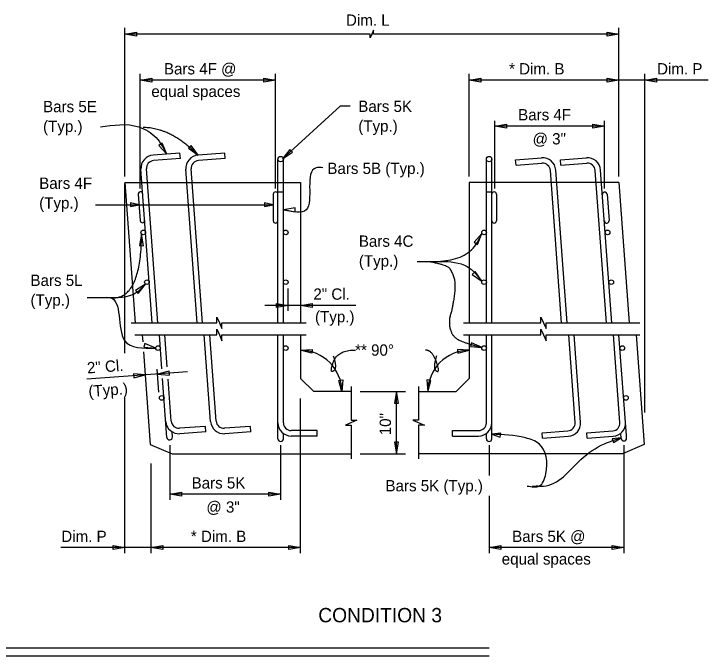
# Model space of a CAD drawing. Extents: x 120790.7 to 120844.8, y 120612.1 to 120653.6.
# Drawn here: x 120810.92 to 120820.21, y 120612.48 to 120621.08 of the extents above; entities that cross this region are included whole.
import ezdxf

# ---------------------------------------------------------------- set-up
doc = ezdxf.new("R2010")
doc.units = 0
for name, color, linetype in [('AdhocPoint_dp', 7, 'Continuous'), ('Patterning', 7, 'Continuous'), ('PlotBorder_dp', 7, 'Continuous'), ('SheetBorder_dp', 7, 'Continuous')]:
    doc.layers.add(name, color=color, linetype=linetype)

# ---------------------------------------------------------------- blocks, each defined once
blk = doc.blocks.new('Terminator-Arrow')
at = {"layer": 'PlotBorder_dp'}
blk.add_lwpolyline([(0, 0), (-0.00041, 0.000069), (-0.00041, -0.000069)], close=True, dxfattribs=at)

msp = doc.modelspace()

# ---------------------------------------------------------------- linework, layer by layer
at = {"layer": 'AdhocPoint_dp'}
for p, q in [((120812.4041, 120618.8231), (120814.7549, 120618.8231)), ((120812.4041, 120618.8231), (120812.5428, 120616.9451)), ((120814.7549, 120618.8231), (120814.7549, 120616.9451)), ((120819.012, 120618.8231), (120817.012, 120618.8231)), ((120817.012, 120618.8231), (120817.012, 120616.9451)), ((120819.012, 120618.8231), (120819.1507, 120616.9451)), ((120812.6373, 120616.7834), (120812.644, 120616.6926)), ((120814.7549, 120616.7834), (120814.7549, 120616.2012)), ((120817.012, 120616.7834), (120817.012, 120616.2012)), ((120819.2452, 120616.7834), (120819.3535, 120615.3161)), ((120812.6539, 120616.559), (120812.7457, 120615.3161)), ((120814.9317, 120616.0244), (120814.7549, 120616.2012)), ((120816.8352, 120616.0244), (120817.012, 120616.2012)), ((120815.4322, 120616.0244), (120814.9317, 120616.0244)), ((120816.3346, 120616.0244), (120816.8352, 120616.0244)), ((120812.7457, 120615.3161), (120813.0374, 120615.1911)), ((120819.3535, 120615.3161), (120819.0619, 120615.1911)), ((120813.0374, 120615.1911), (120815.4322, 120615.1911)), ((120819.0619, 120615.1911), (120816.3346, 120615.1911))]:
    msp.add_line(p, q, dxfattribs=at)
at = {"layer": 'PlotBorder_dp'}
for p, q in [((120812.4041, 120618.9059), (120812.4041, 120620.8956)), ((120812.4041, 120618.9059), (120812.4041, 120620.8956)), ((120819.012, 120618.9059), (120819.012, 120620.8956)), ((120819.012, 120618.9059), (120819.012, 120620.8956)), ((120812.6116, 120618.7443), (120812.6116, 120620.2796)), ((120812.6116, 120618.7443), (120812.6116, 120620.2796)), ((120814.4215, 120618.7443), (120814.4215, 120620.2796)), ((120814.4215, 120618.7443), (120814.4215, 120620.2796)), ((120817.012, 120618.9059), (120817.012, 120620.2796)), ((120817.012, 120618.9059), (120817.012, 120620.2796)), ((120819.3628, 120615.7466), (120819.3628, 120620.2796)), ((120819.3628, 120615.7466), (120819.3628, 120620.2796)), ((120814.4214, 120620.1951), (120812.6115, 120620.1951)), ((120814.4214, 120620.1951), (120812.6115, 120620.1951)), ((120820.2078, 120620.1951), (120817.0118, 120620.1951)), ((120820.2078, 120620.1951), (120817.0118, 120620.1951)), ((120817.3542, 120618.7443), (120817.3542, 120619.6506)), ((120817.3542, 120618.7443), (120817.3542, 120619.6506)), ((120818.823, 120619.58), (120817.3542, 120619.58)), ((120818.823, 120619.58), (120817.3542, 120619.58)), ((120818.823, 120618.7443), (120818.823, 120619.6506)), ((120818.823, 120618.7443), (120818.823, 120619.6506)), ((120812.4041, 120616.5376), (120812.4041, 120618.8093)), ((120812.4041, 120616.5376), (120812.4041, 120618.8093)), ((120812.0106, 120618.527), (120814.3903, 120618.527)), ((120812.0106, 120618.527), (120814.3903, 120618.527)), ((120814.5882, 120617.1047), (120814.5882, 120617.405)), ((120814.5882, 120617.1047), (120814.5882, 120617.405)), ((120815.4972, 120617.1797), (120814.2782, 120617.1797)), ((120815.4972, 120617.1797), (120814.2782, 120617.1797)), ((120812.8612, 120616.0158), (120812.8384, 120616.325)), ((120812.8612, 120616.0158), (120812.8384, 120616.325)), ((120813.2437, 120616.2903), (120811.8962, 120616.1908)), ((120813.2437, 120616.2903), (120811.8962, 120616.1908)), ((120815.5533, 120616.0244), (120816.1614, 120616.0244)), ((120815.5533, 120616.0244), (120816.1614, 120616.0244)), ((120816.0406, 120615.1911), (120816.0406, 120616.0244)), ((120816.0406, 120615.1911), (120816.0406, 120616.0244)), ((120812.4041, 120613.8613), (120812.4041, 120615.9404)), ((120812.4041, 120613.8613), (120812.4041, 120615.9404)), ((120814.7549, 120613.8613), (120814.7549, 120615.9327)), ((120814.7549, 120613.8613), (120814.7549, 120615.9327)), ((120813.0046, 120615.3084), (120813.0046, 120614.5766)), ((120813.0046, 120615.3084), (120813.0046, 120614.5766)), ((120814.4893, 120615.3084), (120814.4893, 120614.5766)), ((120814.4893, 120615.3084), (120814.4893, 120614.5766)), ((120817.2776, 120615.3084), (120817.2776, 120614.9019)), ((120817.2776, 120615.3084), (120817.2776, 120614.9019)), ((120819.0809, 120615.3084), (120819.0809, 120613.8613)), ((120819.0809, 120615.3084), (120819.0809, 120613.8613)), ((120815.5533, 120615.1911), (120816.1614, 120615.1911)), ((120815.5533, 120615.1911), (120816.1614, 120615.1911)), ((120812.7549, 120613.8613), (120812.7549, 120615.0633)), ((120812.7549, 120613.8613), (120812.7549, 120615.0633)), ((120814.4893, 120614.6522), (120813.0046, 120614.6522)), ((120814.4893, 120614.6522), (120813.0046, 120614.6522)), ((120817.2776, 120614.6298), (120817.2776, 120613.8613)), ((120817.2776, 120614.6298), (120817.2776, 120613.8613)), ((120814.7549, 120613.9369), (120811.5492, 120613.9369)), ((120814.7549, 120613.9369), (120811.5492, 120613.9369)), ((120819.0809, 120613.9369), (120817.2776, 120613.9369)), ((120819.0809, 120613.9369), (120817.2776, 120613.9369)), ((120817.2776, 120612.5928), (120809.1791, 120612.5928)), ((120817.2776, 120612.5928), (120809.1791, 120612.5928)), ((120817.2776, 120612.4847), (120809.1791, 120612.4847)), ((120817.2776, 120612.4847), (120809.1791, 120612.4847))]:
    msp.add_line(p, q, dxfattribs=at)
for points in [[(120819.0118, 120620.8104), (120815.7303, 120620.8104), (120815.7303, 120620.8621), (120815.7078, 120620.8104), (120815.6853, 120620.7588), (120815.6853, 120620.8104), (120812.404, 120620.8104)], [(120819.0118, 120620.8104), (120815.7303, 120620.8104), (120815.7303, 120620.8621), (120815.7078, 120620.8104), (120815.6853, 120620.7588), (120815.6853, 120620.8104), (120812.404, 120620.8104)], [(120815.419, 120619.8458), (120815.286, 120619.8458), (120814.5144, 120619.1427)], [(120815.419, 120619.8458), (120815.286, 120619.8458), (120814.5144, 120619.1427)], [(120812.4899, 120616.9451), (120813.6369, 120616.9451), (120813.6369, 120617.0226), (120813.6707, 120616.9451), (120813.7044, 120616.8676), (120813.7044, 120616.9451), (120814.8305, 120616.9451)], [(120812.4899, 120616.9451), (120813.6369, 120616.9451), (120813.6369, 120617.0226), (120813.6707, 120616.9451), (120813.7044, 120616.8676), (120813.7044, 120616.9451), (120814.8305, 120616.9451)], [(120816.9364, 120616.9451), (120817.9717, 120616.9451), (120817.9717, 120617.0226), (120818.0054, 120616.9451), (120818.0392, 120616.8676), (120818.0392, 120616.9451), (120819.2965, 120616.9451)], [(120816.9364, 120616.9451), (120817.9717, 120616.9451), (120817.9717, 120617.0226), (120818.0054, 120616.9451), (120818.0392, 120616.8676), (120818.0392, 120616.9451), (120819.2965, 120616.9451)], [(120812.5373, 120616.7834), (120813.6369, 120616.7834), (120813.6369, 120616.8609), (120813.6707, 120616.7834), (120813.7044, 120616.7059), (120813.7044, 120616.7834), (120814.8305, 120616.7834)], [(120812.5373, 120616.7834), (120813.6369, 120616.7834), (120813.6369, 120616.8609), (120813.6707, 120616.7834), (120813.7044, 120616.7059), (120813.7044, 120616.7834), (120814.8305, 120616.7834)], [(120816.9364, 120616.7834), (120817.9717, 120616.7834), (120817.9717, 120616.8609), (120818.0054, 120616.7834), (120818.0392, 120616.7059), (120818.0392, 120616.7834), (120819.2965, 120616.7834)], [(120816.9364, 120616.7834), (120817.9717, 120616.7834), (120817.9717, 120616.8609), (120818.0054, 120616.7834), (120818.0392, 120616.7059), (120818.0392, 120616.7834), (120819.2965, 120616.7834)], [(120815.4322, 120616.0915), (120815.4322, 120615.6415), (120815.5097, 120615.6415), (120815.3547, 120615.574), (120815.4322, 120615.574), (120815.4322, 120615.124)], [(120815.4322, 120616.0915), (120815.4322, 120615.6415), (120815.5097, 120615.6415), (120815.3547, 120615.574), (120815.4322, 120615.574), (120815.4322, 120615.124)], [(120816.3346, 120616.0915), (120816.3346, 120615.6415), (120816.2571, 120615.6415), (120816.4121, 120615.574), (120816.3346, 120615.574), (120816.3346, 120615.124)], [(120816.3346, 120616.0915), (120816.3346, 120615.6415), (120816.2571, 120615.6415), (120816.4121, 120615.574), (120816.3346, 120615.574), (120816.3346, 120615.124)]]:
    msp.add_lwpolyline(points, dxfattribs=at)
for points in [[(120812.9647, 120619.2035), (120812.9026, 120619.3492), (120812.8581, 120619.3207)], [(120812.9647, 120619.2035), (120812.9026, 120619.3492), (120812.8581, 120619.3207)], [(120813.3849, 120619.19), (120813.2935, 120619.3194), (120813.256, 120619.282)], [(120813.3849, 120619.19), (120813.2935, 120619.3194), (120813.256, 120619.282)], [(120814.5144, 120619.1428), (120814.6477, 120619.2284), (120814.6121, 120619.2675)], [(120814.5144, 120619.1428), (120814.6477, 120619.2284), (120814.6121, 120619.2675)], [(120812.5958, 120618.527), (120812.4786, 120618.5535), (120812.4786, 120618.5005)], [(120812.5958, 120618.527), (120812.4786, 120618.5535), (120812.4786, 120618.5005)], [(120814.3903, 120618.527), (120814.2732, 120618.5535), (120814.2732, 120618.5005)], [(120814.3903, 120618.527), (120814.2732, 120618.5535), (120814.2732, 120618.5005)], [(120814.5257, 120618.4585), (120814.6819, 120618.432), (120814.6819, 120618.485)], [(120814.5257, 120618.4585), (120814.6819, 120618.432), (120814.6819, 120618.485)], [(120812.6297, 120618.1344), (120812.6016, 120617.9785), (120812.6546, 120617.9779)], [(120812.6297, 120618.1344), (120812.6016, 120617.9785), (120812.6546, 120617.9779)], [(120817.1821, 120618.1422), (120817.0763, 120618.0242), (120817.1211, 120617.996)], [(120817.1821, 120618.1422), (120817.0763, 120618.0242), (120817.1211, 120617.996)], [(120817.1817, 120617.5033), (120817.0896, 120617.6322), (120817.0523, 120617.5947)], [(120817.1817, 120617.5033), (120817.0896, 120617.6322), (120817.0523, 120617.5947)], [(120812.682, 120617.4651), (120812.5494, 120617.3784), (120812.5853, 120617.3396)], [(120812.682, 120617.4651), (120812.5494, 120617.3784), (120812.5853, 120617.3396)], [(120812.8175, 120616.6078), (120812.6721, 120616.6707), (120812.6595, 120616.6193)], [(120812.8175, 120616.6078), (120812.6721, 120616.6707), (120812.6595, 120616.6193)], [(120817.1869, 120616.6139), (120817.0423, 120616.6784), (120817.0291, 120616.6272)], [(120817.1869, 120616.6139), (120817.0423, 120616.6784), (120817.0291, 120616.6272)], [(120814.7548, 120616.5779), (120814.9127, 120616.5909), (120814.9082, 120616.5382)], [(120814.7548, 120616.5779), (120814.9127, 120616.5909), (120814.9082, 120616.5382)], [(120817.012, 120616.5779), (120816.8541, 120616.5909), (120816.8586, 120616.5382)], [(120817.012, 120616.5779), (120816.8541, 120616.5909), (120816.8586, 120616.5382)], [(120812.6768, 120616.2485), (120812.5191, 120616.2633), (120812.523, 120616.2106)], [(120812.6768, 120616.2485), (120812.5191, 120616.2633), (120812.523, 120616.2106)], [(120812.8431, 120616.2607), (120813.0008, 120616.2459), (120812.9969, 120616.2986)], [(120812.8431, 120616.2607), (120813.0008, 120616.2459), (120812.9969, 120616.2986)], [(120815.3096, 120616.0226), (120815.2685, 120616.1755), (120815.3212, 120616.1806)], [(120815.3096, 120616.0226), (120815.2685, 120616.1755), (120815.3212, 120616.1806)], [(120816.4572, 120616.0226), (120816.4984, 120616.1755), (120816.4457, 120616.1806)], [(120816.4572, 120616.0226), (120816.4984, 120616.1755), (120816.4457, 120616.1806)], [(120816.0406, 120616.0244), (120816.0142, 120615.8683), (120816.0671, 120615.8683)], [(120816.0406, 120616.0244), (120816.0142, 120615.8683), (120816.0671, 120615.8683)], [(120817.3141, 120615.455), (120817.4276, 120615.4159), (120817.4334, 120615.4686)], [(120817.3141, 120615.455), (120817.4276, 120615.4159), (120817.4334, 120615.4686)], [(120819.044, 120615.4064), (120818.9248, 120615.3918), (120818.9426, 120615.342)], [(120819.044, 120615.4064), (120818.9248, 120615.3918), (120818.9426, 120615.342)], [(120816.0406, 120615.1912), (120816.0671, 120615.3474), (120816.0142, 120615.3474)], [(120816.0406, 120615.1912), (120816.0671, 120615.3474), (120816.0142, 120615.3474)]]:
    msp.add_lwpolyline(points, close=True, dxfattribs=at)
for centre, start, end in [((120814.7505, 120616.0187), 0.39914, 89.54996), ((120814.7505, 120616.0187), 0.39914, 89.54996), ((120817.0164, 120616.0187), 90.45004, 179.60086), ((120817.0164, 120616.0187), 90.45004, 179.60086)]:
    msp.add_arc(centre, 0.5592, start, end, dxfattribs=at)
for points in [[(120812.0777, 120619.5681), (120812.5921, 120619.5681), (120812.8222, 120619.4255), (120812.9647, 120619.2034)], [(120812.0777, 120619.5681), (120812.5921, 120619.5681), (120812.8222, 120619.4255), (120812.9647, 120619.2034)], [(120815.0537, 120619.0206), (120814.9639, 120619.0206), (120814.8318, 120618.4585), (120814.5257, 120618.4585)], [(120815.0537, 120619.0206), (120814.9639, 120619.0206), (120814.8318, 120618.4585), (120814.5257, 120618.4585)], [(120816.3169, 120617.7672), (120816.5689, 120617.7672), (120817.0443, 120617.9239), (120817.1821, 120618.1422)], [(120816.3169, 120617.7672), (120816.5689, 120617.7672), (120817.0443, 120617.9239), (120817.1821, 120618.1422)], [(120816.4395, 120617.7672), (120816.6303, 120617.7684), (120816.9865, 120617.6975), (120817.1817, 120617.5033)], [(120816.4395, 120617.7672), (120816.6303, 120617.7684), (120816.9865, 120617.6975), (120817.1817, 120617.5033)], [(120811.9008, 120617.2836), (120812.15, 120617.2836), (120812.5629, 120617.3549), (120812.682, 120617.4651)], [(120811.9008, 120617.2836), (120812.15, 120617.2836), (120812.5629, 120617.3549), (120812.682, 120617.4651)], [(120812.1078, 120617.2836), (120812.202, 120617.2841), (120812.4011, 120616.71), (120812.8175, 120616.6078)], [(120812.1078, 120617.2836), (120812.202, 120617.2841), (120812.4011, 120616.71), (120812.8175, 120616.6078)], [(120817.7874, 120614.7615), (120817.949, 120614.7615), (120818.0366, 120614.926), (120817.9462, 120615.3261), (120817.7655, 120615.4056), (120817.3141, 120615.4549)], [(120817.7874, 120614.7615), (120817.949, 120614.7615), (120818.0366, 120614.926), (120817.9462, 120615.3261), (120817.7655, 120615.4056), (120817.3141, 120615.4549)], [(120817.8559, 120614.7615), (120817.9627, 120614.7615), (120818.0038, 120614.7615), (120818.505, 120615.1151), (120818.8199, 120615.3261), (120819.044, 120615.4064)], [(120817.8559, 120614.7615), (120817.9627, 120614.7615), (120818.0038, 120614.7615), (120818.505, 120615.1151), (120818.8199, 120615.3261), (120819.044, 120615.4064)]]:
    msp.add_spline(points, degree=3, dxfattribs=at)
for points in [[(120813.3844, 120619.1901), (120813.0161, 120619.56), (120812.6479, 120619.56)], [(120813.3844, 120619.1901), (120813.0161, 120619.56), (120812.6479, 120619.56)], [(120812.2537, 120617.281), (120812.6208, 120617.281), (120812.6297, 120618.1344)], [(120812.2537, 120617.281), (120812.6208, 120617.281), (120812.6297, 120618.1344)], [(120816.4786, 120617.7674), (120816.6985, 120617.7219), (120816.7732, 120617.6566), (120816.8354, 120617.4605), (120816.7856, 120617.1368), (120816.7483, 120617.0216), (120816.7483, 120616.9376), (120816.7483, 120616.8847), (120816.8012, 120616.7508), (120816.9692, 120616.6699), (120817.1869, 120616.6139)], [(120816.4786, 120617.7674), (120816.6985, 120617.7219), (120816.7732, 120617.6566), (120816.8354, 120617.4605), (120816.7856, 120617.1368), (120816.7483, 120617.0216), (120816.7483, 120616.9376), (120816.7483, 120616.8847), (120816.8012, 120616.7508), (120816.9692, 120616.6699), (120817.1869, 120616.6139)], [(120815.1927, 120616.5051), (120815.25, 120616.3332), (120815.1393, 120616.2645), (120815.2519, 120616.5815), (120815.4918, 120616.5815)], [(120815.1927, 120616.5051), (120815.25, 120616.3332), (120815.1393, 120616.2645), (120815.2519, 120616.5815), (120815.4918, 120616.5815)], [(120816.5761, 120616.5051), (120816.5188, 120616.3332), (120816.6295, 120616.2645), (120816.5169, 120616.5815), (120816.426, 120616.5815)], [(120816.5761, 120616.5051), (120816.5188, 120616.3332), (120816.6295, 120616.2645), (120816.5169, 120616.5815), (120816.426, 120616.5815)]]:
    msp.add_open_spline(points, degree=2, dxfattribs=at)
at = {"layer": 'SheetBorder_dp'}
for p, q in [((120813.1426, 120619.2166), (120812.7844, 120619.1901)), ((120813.1479, 120619.1438), (120813.1426, 120619.2166)), ((120813.7426, 120619.2166), (120813.3844, 120619.1901)), ((120813.7479, 120619.1438), (120813.7426, 120619.2166)), ((120813.1479, 120619.1438), (120812.7897, 120619.1174)), ((120813.7479, 120619.1438), (120813.3897, 120619.1174)), ((120814.4528, 120616.9451), (120814.4528, 120619.1363)), ((120814.5257, 120616.9451), (120814.5257, 120619.1363)), ((120817.2411, 120616.9451), (120817.2411, 120619.1363)), ((120817.3141, 120616.9451), (120817.3141, 120619.1363)), ((120817.6332, 120619.1292), (120817.9801, 120619.1548)), ((120817.6386, 120619.0565), (120817.6332, 120619.1292)), ((120818.2332, 120619.1292), (120818.5801, 120619.1548)), ((120818.2386, 120619.0565), (120818.2332, 120619.1292)), ((120817.6386, 120619.0565), (120817.9855, 120619.0821)), ((120818.2386, 120619.0565), (120818.5855, 120619.0821)), ((120812.7725, 120616.9451), (120812.6208, 120619.0004)), ((120812.8457, 120616.9451), (120812.6935, 120619.0058)), ((120813.3725, 120616.9451), (120813.2208, 120619.0004)), ((120813.4457, 120616.9451), (120813.2935, 120619.0058)), ((120818.2478, 120616.9451), (120818.0971, 120618.9858)), ((120818.3209, 120616.9451), (120818.1698, 120618.9912)), ((120818.8478, 120616.9451), (120818.6971, 120618.9858)), ((120818.9209, 120616.9451), (120818.7698, 120618.9912)), ((120812.5827, 120618.6669), (120812.6088, 120618.3137)), ((120814.3903, 120618.6669), (120814.3903, 120618.3127)), ((120814.4528, 120618.6981), (120814.5257, 120618.6981)), ((120817.2411, 120618.6981), (120817.3141, 120618.6981)), ((120817.3766, 120618.6669), (120817.3766, 120618.3127)), ((120818.8564, 120618.6669), (120818.8825, 120618.3137)), ((120812.9004, 120616.3311), (120812.867, 120616.7834)), ((120812.9718, 120616.3554), (120812.9402, 120616.7834)), ((120813.5525, 120615.6255), (120813.467, 120616.7834)), ((120813.6253, 120615.6309), (120813.5402, 120616.7834)), ((120814.4528, 120615.3942), (120814.4528, 120616.7834)), ((120814.5257, 120615.6078), (120814.5257, 120616.7834)), ((120817.2411, 120615.6078), (120817.2411, 120616.7834)), ((120817.3141, 120615.4307), (120817.3141, 120616.7834)), ((120818.4288, 120615.611), (120818.3423, 120616.7834)), ((120818.5016, 120615.6163), (120818.4154, 120616.7834)), ((120819.0288, 120615.611), (120818.9423, 120616.7834)), ((120819.1146, 120615.4397), (120819.0154, 120616.7834)), ((120812.9683, 120615.4126), (120812.9102, 120616.1984)), ((120813.0253, 120615.6309), (120812.9838, 120616.1922)), ((120813.041, 120615.4179), (120813.0358, 120615.4881)), ((120813.4838, 120615.5603), (120813.1369, 120615.5347)), ((120813.4892, 120615.4876), (120813.1422, 120615.462)), ((120813.4892, 120615.4876), (120813.4838, 120615.5603)), ((120814.0838, 120615.5603), (120813.7369, 120615.5347)), ((120814.0892, 120615.4876), (120813.7422, 120615.462)), ((120814.0892, 120615.4876), (120814.0838, 120615.5603)), ((120814.9778, 120615.5036), (120814.6299, 120615.5036)), ((120814.9778, 120615.4307), (120814.9778, 120615.5036)), ((120816.7891, 120615.5036), (120817.1369, 120615.5036)), ((120816.7891, 120615.4307), (120816.7891, 120615.5036)), ((120817.9857, 120615.4738), (120818.3326, 120615.4994)), ((120818.5857, 120615.4738), (120818.9326, 120615.4994)), ((120814.5257, 120615.3942), (120814.5257, 120615.4646)), ((120814.9778, 120615.4307), (120814.6299, 120615.4307)), ((120816.7891, 120615.4307), (120817.1369, 120615.4307)), ((120817.2411, 120615.3942), (120817.2411, 120615.4646)), ((120817.3141, 120615.3942), (120817.3141, 120615.4307)), ((120817.991, 120615.401), (120817.9857, 120615.4738)), ((120817.991, 120615.401), (120818.338, 120615.4267)), ((120818.591, 120615.401), (120818.5857, 120615.4738)), ((120818.591, 120615.401), (120818.938, 120615.4267)), ((120819.0446, 120615.398), (120819.0394, 120615.4681)), ((120819.1173, 120615.4033), (120819.1146, 120615.4397))]:
    msp.add_line(p, q, dxfattribs=at)
for centre, radius in [((120814.4893, 120619.1374), 0.0365), ((120817.2776, 120619.1374), 0.0365), ((120812.6518, 120618.1565), 0.0312), ((120814.557, 120618.1565), 0.0312), ((120817.2099, 120618.1565), 0.0312), ((120818.8627, 120618.1565), 0.0312), ((120812.7011, 120617.4898), 0.0312), ((120814.557, 120617.4898), 0.0312), ((120817.2099, 120617.4898), 0.0312), ((120818.9119, 120617.4898), 0.0312), ((120812.8488, 120616.6078), 0.0312), ((120814.557, 120616.6078), 0.0312), ((120817.2099, 120616.6078), 0.0312), ((120819.0596, 120616.6078), 0.0312), ((120812.898, 120615.9411), 0.0312), ((120819.1088, 120615.9411), 0.0312)]:
    msp.add_circle(centre, radius, dxfattribs=at)
for centre, radius, start, end in [((120812.7974, 120619.0135), 0.1771, 94.22341, 184.22341), ((120812.7974, 120619.0135), 0.1042, 94.22341, 184.22341), ((120813.3974, 120619.0135), 0.1771, 94.22341, 184.22341), ((120813.3974, 120619.0135), 0.1042, 94.22341, 184.22341), ((120817.9932, 120618.9782), 0.1771, 4.22317, 94.22317), ((120818.5932, 120618.9782), 0.1771, 4.22317, 94.22317), ((120817.9932, 120618.9782), 0.1042, 4.22317, 94.22317), ((120818.5932, 120618.9782), 0.1042, 4.22317, 94.22317), ((120812.6139, 120618.6692), 0.0312, 4.22341, 184.22341), ((120814.4215, 120618.6669), 0.0312, 0, 180), ((120817.3453, 120618.6669), 0.0312, 0, 180), ((120818.8253, 120618.6646), 0.0312, 4.22317, 184.22317), ((120812.64, 120618.316), 0.0312, 184.22341, 4.22341), ((120814.4215, 120618.3127), 0.0312, 180, 0), ((120817.3453, 120618.3127), 0.0312, 180, 0), ((120818.8513, 120618.3114), 0.0312, 184.22317, 4.22317), ((120813.1292, 120615.6386), 0.1771, 184.22341, 274.22341), ((120813.1292, 120615.6386), 0.1042, 184.22341, 274.22341), ((120813.7292, 120615.6386), 0.1771, 184.22341, 274.22341), ((120813.7292, 120615.6386), 0.1042, 184.22341, 274.22341), ((120814.6299, 120615.6078), 0.1771, 180, 270), ((120814.6299, 120615.6078), 0.1042, 180, 270), ((120817.1369, 120615.6078), 0.1042, 270, 0), ((120817.1369, 120615.6078), 0.1771, 270, 0), ((120818.3249, 120615.6033), 0.1042, 274.22317, 4.22317), ((120818.3249, 120615.6033), 0.1771, 274.22317, 4.22317), ((120818.9249, 120615.6033), 0.1042, 274.22317, 4.22317), ((120818.9249, 120615.6033), 0.1771, 274.22317, 4.22317), ((120813.0046, 120615.4152), 0.0365, 184.22341, 4.22341), ((120814.4893, 120615.3942), 0.0365, 180, 0), ((120817.2776, 120615.3942), 0.0365, 180, 0), ((120819.0809, 120615.4007), 0.0365, 184.22317, 4.22317)]:
    msp.add_arc(centre, radius, start, end, dxfattribs=at)

# ---------------------------------------------------------------- block references
at = {"layer": 'PlotBorder_dp', "xscale": 381, "yscale": -384.0238095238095, "rotation": 180}
for p in [(120812.4038, 120620.81), (120812.4038, 120620.81), (120812.6114, 120620.1947), (120812.6114, 120620.1947), (120817.0117, 120620.1947), (120817.0117, 120620.1947), (120819.3626, 120620.195), (120819.3626, 120620.195), (120817.3541, 120619.5797), (120817.3541, 120619.5797), (120814.755, 120617.1792), (120814.755, 120617.1792), (120813.0045, 120614.6518), (120813.0045, 120614.6518), (120812.7547, 120613.9366), (120812.7547, 120613.9366), (120817.2776, 120613.9366), (120817.2776, 120613.9366)]:
    msp.add_blockref('Terminator-Arrow', p, dxfattribs=at)
at = {"layer": 'PlotBorder_dp', "xscale": 381, "yscale": -384.0238095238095}
for p in [(120819.0117, 120620.8099), (120819.0117, 120620.8099), (120814.4213, 120620.1947), (120814.4213, 120620.1947), (120819.0117, 120620.1947), (120819.0117, 120620.1947), (120818.8229, 120619.5797), (120818.8229, 120619.5797), (120814.5884, 120617.1792), (120814.5884, 120617.1792), (120814.4892, 120614.6518), (120814.4892, 120614.6518), (120812.404, 120613.9366), (120812.404, 120613.9366), (120814.7548, 120613.9366), (120814.7548, 120613.9366), (120819.0809, 120613.9366), (120819.0809, 120613.9366)]:
    msp.add_blockref('Terminator-Arrow', p, dxfattribs=at)

# ---------------------------------------------------------------- texts
at = {"layer": 'Patterning'}
for s, height, p in [('Dim. L', 0.1512, (120815.3631, 120620.9216)), ('Bars 4F @', 0.1512, (120812.9282, 120620.2703)), ('* Dim. B', 0.1512, (120817.545, 120620.2702)), ('Dim. P', 0.1512, (120819.5252, 120620.2702)), ('equal spaces', 0.1512, (120812.7593, 120619.9682)), ('Bars 4F', 0.1512, (120817.6666, 120619.6553)), ('@ 3"', 0.1512, (120817.8598, 120619.3332)), ('Bars 5B (Typ.)', 0.1512, (120815.1138, 120618.9377)), ('2" Cl.', 0.1512, (120814.9272, 120617.2549)), ('(Typ.)', 0.1512, (120814.949, 120616.9524)), ('** 90°', 0.1512, (120815.4853, 120616.5056)), ('Bars 5K', 0.1512, (120813.2981, 120614.7274)), ('Bars 5K (Typ.)', 0.1512, (120815.8918, 120614.69)), ('@ 3"', 0.1512, (120813.4959, 120614.4053)), ('Dim. P', 0.1512, (120811.5549, 120614.0122)), ('* Dim. B', 0.1512, (120813.2881, 120614.0122)), ('Bars 5K @', 0.1512, (120817.5866, 120614.0122)), ('equal spaces', 0.1512, (120817.4468, 120613.71)), ('CONDITION 3', 0.192, (120814.9929, 120612.9373))]:
    msp.add_text(s, height=height, dxfattribs=at).set_placement(p)
for s, rotation, p in [('2" Cl.', 4.22341, (120811.9046, 120616.2672)), ('(Typ.)', 4.22341, (120811.9234, 120615.9532)), ('10"', 90, (120815.9649, 120615.4409))]:
    msp.add_text(s, height=0.1512, rotation=rotation, dxfattribs=at).set_placement(p)
at = {"layer": 'PlotBorder_dp'}
for s, p in [('Bars 5E', (120811.311, 120619.7645)), ('Bars 5K', (120815.5276, 120619.7682)), ('(Typ.)', (120811.311, 120619.5005)), ('(Typ.)', (120815.5276, 120619.5042)), ('Bars 4F', (120811.2591, 120618.7391)), ('(Typ.)', (120811.2591, 120618.4751)), ('Bars 4C', (120815.5355, 120617.9634)), ('(Typ.)', (120815.5355, 120617.6993)), ('Bars 5L', (120811.1427, 120617.4393)), ('(Typ.)', (120811.1427, 120617.1753))]:
    msp.add_text(s, height=0.1512, dxfattribs=at).set_placement(p)

doc.saveas('drawing.dxf')
